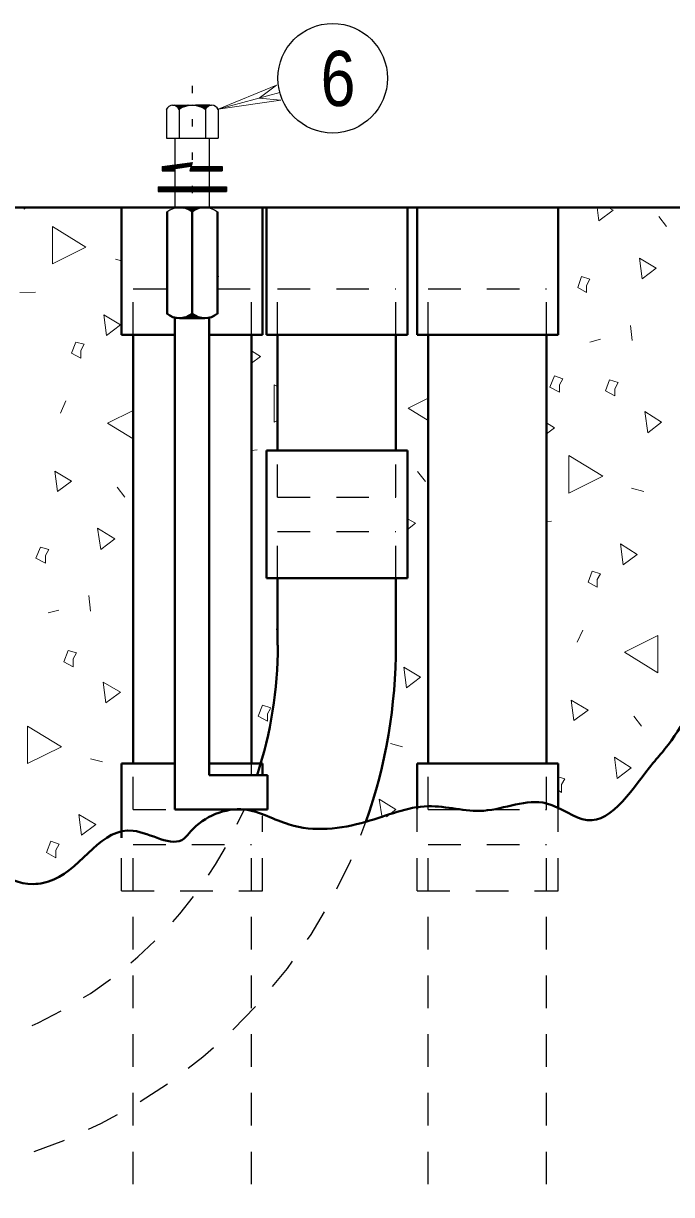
# Model space of a CAD drawing. Extents: x 312583 to 312854, y 144419 to 144597.
# Drawn here: x 312745.49 to 312754.44, y 144531.37 to 144547.52 of the extents above; entities that cross this region are included whole.
import ezdxf

# ---------------------------------------------------------------- set-up
doc = ezdxf.new("R2010")
doc.units = 0
doc.header["$LTSCALE"] = 0.3
doc.linetypes.add('DOTTED', pattern=[1.5, 0.3, -1.2])
doc.linetypes.add('SHORT_DASHED', pattern=[2.7, 1.5, -1.2])
doc.layers.add('1', color=7, linetype='Continuous', lineweight=25)
doc.layers.add('2', color=7, linetype='Continuous', lineweight=13)

msp = doc.modelspace()

# ---------------------------------------------------------------- linework, layer by layer
at = {"layer": '1', "linetype": 'DOTTED'}
msp.add_line((312747.8218, 144546.6623), (312747.8218, 144544.9833), dxfattribs=at)
at = {"layer": '1'}
for p, q in [((312747.4691, 144546.3403), (312747.4691, 144545.9416)), ((312747.5535, 144546.3939), (312748.0901, 144546.3939)), ((312747.6455, 144546.3403), (312747.6455, 144545.9416)), ((312748.0058, 144546.3403), (312748.0058, 144545.9416)), ((312748.1821, 144546.3403), (312748.1821, 144545.9416)), ((312747.4691, 144545.9416), (312748.1821, 144545.9416)), ((312747.5841, 144545.9416), (312747.5841, 144544.9833)), ((312748.0595, 144545.9416), (312748.0595, 144544.9833)), ((312747.4078, 144545.5506), (312747.4078, 144545.4893)), ((312747.8065, 144545.5506), (312748.2358, 144545.5506)), ((312748.2358, 144545.5506), (312748.2358, 144545.4893)), ((312747.7911, 144545.4893), (312748.2358, 144545.4893)), ((312747.3541, 144545.2669), (312748.2971, 144545.2669)), ((312747.3541, 144545.2669), (312747.3541, 144545.2056)), ((312747.3541, 144545.2516), (312748.2971, 144545.2516)), ((312747.3541, 144545.2363), (312748.2971, 144545.2363)), ((312747.3541, 144545.2209), (312748.2971, 144545.2209)), ((312747.3541, 144545.2056), (312748.2971, 144545.2056)), ((312748.2971, 144545.2669), (312748.2971, 144545.2056)), ((312747.5841, 144544.9833), (312748.0595, 144544.9833)), ((312747.6531, 144544.9833), (312747.9981, 144544.9833))]:
    msp.add_line(p, q, dxfattribs=at)
at = {"layer": '1', "lineweight": 40}
for p, q in [((312722.2688, 144544.9833), (312760.6021, 144544.9833)), ((312746.8481, 144543.2276), (312746.8481, 144544.9833)), ((312747.4768, 144544.9219), (312747.4768, 144543.5189)), ((312747.8218, 144544.9833), (312747.8218, 144543.4576)), ((312748.1745, 144544.9219), (312748.1745, 144543.5189)), ((312748.7955, 144543.2276), (312748.7955, 144544.9833)), ((312748.8491, 144543.2276), (312748.8491, 144544.9833)), ((312750.7965, 144543.2276), (312750.7965, 144544.9833)), ((312750.9268, 144543.2276), (312750.9268, 144544.9833)), ((312752.8741, 144543.2276), (312752.8741, 144544.9833)), ((312747.5841, 144543.4576), (312747.5841, 144536.6803)), ((312747.6531, 144543.4576), (312747.9981, 144543.4576)), ((312748.0595, 144543.4576), (312748.0595, 144537.1556)), ((312746.8481, 144543.2276), (312747.5841, 144543.2276)), ((312747.0091, 144537.3166), (312747.0091, 144543.2276)), ((312748.0595, 144543.2276), (312748.7955, 144543.2276)), ((312748.6421, 144537.3166), (312748.6421, 144543.2276)), ((312748.8491, 144543.2276), (312750.7965, 144543.2276)), ((312749.0025, 144541.6329), (312749.0025, 144543.2276)), ((312750.6355, 144541.6329), (312750.6355, 144543.2276)), ((312750.9268, 144543.2276), (312752.8741, 144543.2276)), ((312751.0801, 144537.3166), (312751.0801, 144543.2276)), ((312752.7131, 144537.3166), (312752.7131, 144543.2276)), ((312748.8491, 144539.8696), (312748.8491, 144541.6329)), ((312748.8491, 144541.6329), (312750.7965, 144541.6329)), ((312750.7965, 144539.8696), (312750.7965, 144541.6329)), ((312748.8491, 144539.8696), (312750.7965, 144539.8696)), ((312749.0025, 144538.9496), (312749.0025, 144539.8696)), ((312750.6355, 144538.9496), (312750.6355, 144539.8696)), ((312746.8481, 144537.3166), (312747.5841, 144537.3166)), ((312746.8481, 144536.2893), (312746.8481, 144537.3166)), ((312748.0595, 144537.3166), (312748.7955, 144537.3166)), ((312748.7955, 144537.1556), (312748.7955, 144537.3166)), ((312750.9268, 144537.3166), (312752.8741, 144537.3166)), ((312750.9268, 144536.6879), (312750.9268, 144537.3166)), ((312752.8741, 144536.6956), (312752.8741, 144537.3166)), ((312748.0595, 144537.1556), (312748.8645, 144537.1556)), ((312748.8645, 144537.1556), (312748.8645, 144536.6803)), ((312747.5841, 144536.6803), (312748.8645, 144536.6803))]:
    msp.add_line(p, q, dxfattribs=at)
at = {"layer": '1', "lineweight": 13}
msp.add_line((312748.1745, 144544.0403), (312748.1898, 144544.0326), dxfattribs=at)
at = {"layer": '1', "linetype": 'SHORT_DASHED'}
for p, q in [((312747.0091, 144543.2276), (312747.0091, 144543.8639)), ((312747.0091, 144543.8639), (312747.4768, 144543.8639)), ((312748.1745, 144543.8639), (312748.6421, 144543.8639)), ((312748.6421, 144543.2276), (312748.6421, 144543.8639)), ((312749.0025, 144543.8639), (312750.6355, 144543.8639)), ((312749.0025, 144543.2276), (312749.0025, 144543.8639)), ((312750.6355, 144543.2276), (312750.6355, 144543.8639)), ((312751.0801, 144543.8639), (312752.7131, 144543.8639)), ((312751.0801, 144543.2276), (312751.0801, 144543.8639)), ((312752.7131, 144543.2276), (312752.7131, 144543.8639)), ((312749.0025, 144540.9889), (312749.0025, 144541.6329)), ((312750.6355, 144540.9889), (312750.6355, 144541.6329)), ((312749.0025, 144540.9889), (312750.6355, 144540.9889)), ((312749.0025, 144540.5136), (312750.6355, 144540.5136)), ((312749.0025, 144539.8696), (312749.0025, 144540.5136)), ((312750.6355, 144539.8696), (312750.6355, 144540.5136)), ((312747.0091, 144536.6803), (312747.0091, 144537.3166)), ((312748.6421, 144537.1556), (312748.6421, 144537.3166)), ((312751.0801, 144536.6803), (312751.0801, 144537.3166)), ((312752.7131, 144536.6803), (312752.7131, 144537.3166)), ((312747.0091, 144536.6803), (312747.5841, 144536.6803)), ((312748.0595, 144536.6803), (312748.6421, 144536.6803)), ((312750.9268, 144535.5609), (312750.9268, 144536.6879)), ((312751.0801, 144536.6803), (312752.7131, 144536.6803)), ((312752.8741, 144535.5609), (312752.8741, 144536.6956)), ((312748.7955, 144535.5609), (312748.7955, 144536.5959)), ((312746.8481, 144535.5609), (312746.8481, 144536.2893)), ((312747.0091, 144535.5609), (312747.0091, 144536.1973)), ((312747.0091, 144536.1973), (312748.6421, 144536.1973)), ((312748.6421, 144535.5609), (312748.6421, 144536.1973)), ((312751.0801, 144536.1973), (312752.7131, 144536.1973)), ((312751.0801, 144535.5609), (312751.0801, 144536.1973)), ((312752.7131, 144535.5609), (312752.7131, 144536.1973)), ((312746.8481, 144535.5609), (312748.7955, 144535.5609)), ((312747.0091, 144524.2219), (312747.0091, 144535.5609)), ((312748.6421, 144524.2219), (312748.6421, 144535.5609)), ((312750.9268, 144535.5609), (312752.8741, 144535.5609)), ((312751.0801, 144524.2219), (312751.0801, 144535.5609)), ((312752.7131, 144524.2219), (312752.7131, 144535.5609))]:
    msp.add_line(p, q, dxfattribs=at)
at = {"layer": '1'}
for points in [[(312747.5765, 144546.3939), (312747.7758, 144546.3939), (312747.7451, 144546.3863), (312747.7221, 144546.3786), (312747.6838, 144546.3633), (312747.6455, 144546.3403), (312747.6301, 144546.3633), (312747.6148, 144546.3786), (312747.5841, 144546.3939), (312747.7605, 144546.3939), (312747.7145, 144546.3786), (312747.6761, 144546.3633), (312747.6455, 144546.3479), (312747.6225, 144546.3709), (312747.5995, 144546.3863), (312747.7375, 144546.3863), (312747.6915, 144546.3709), (312747.6455, 144546.3479), (312747.6071, 144546.3863), (312747.7221, 144546.3863), (312747.6455, 144546.3556), (312747.6148, 144546.3863), (312747.7145, 144546.3863), (312747.6455, 144546.3556), (312747.6225, 144546.3786), (312747.6991, 144546.3786), (312747.6455, 144546.3633), (312747.6301, 144546.3786), (312747.6761, 144546.3786), (312747.6455, 144546.3709), (312747.6378, 144546.3786), (312747.6608, 144546.3786), (312747.6455, 144546.3709)], [(312748.0671, 144546.3939), (312747.8678, 144546.3939), (312747.9061, 144546.3863), (312747.9291, 144546.3786), (312747.9675, 144546.3633), (312748.0058, 144546.3403), (312748.0135, 144546.3633), (312748.0288, 144546.3786), (312748.0595, 144546.3939), (312747.8831, 144546.3939), (312747.9368, 144546.3786), (312747.9751, 144546.3633), (312747.9981, 144546.3479), (312748.0288, 144546.3709), (312748.0518, 144546.3863), (312747.9061, 144546.3863), (312747.9598, 144546.3709), (312747.9981, 144546.3479), (312748.0365, 144546.3863), (312747.9215, 144546.3863), (312748.0058, 144546.3556), (312748.0365, 144546.3863), (312747.9368, 144546.3863), (312748.0058, 144546.3556), (312748.0211, 144546.3786), (312747.9521, 144546.3786), (312748.0058, 144546.3633), (312748.0135, 144546.3786), (312747.9675, 144546.3786), (312747.9981, 144546.3709), (312748.0058, 144546.3786), (312747.9905, 144546.3786), (312747.9981, 144546.3709)], [(312747.4078, 144545.5506), (312747.8218, 144545.6043), (312747.7911, 144545.4893)], [(312747.8065, 144545.5506), (312747.4078, 144545.4893), (312747.5841, 144545.4893)], [(312747.5841, 144545.4893), (312747.4155, 144545.4969), (312747.4155, 144545.5429), (312747.8141, 144545.5966), (312747.7988, 144545.5506), (312747.5841, 144545.5199), (312747.5765, 144545.4969), (312747.4231, 144545.5046), (312747.4231, 144545.5353), (312747.8065, 144545.5889), (312747.7911, 144545.5583), (312747.5765, 144545.5199), (312747.5688, 144545.5046), (312747.4231, 144545.5123), (312747.4231, 144545.5276), (312747.7911, 144545.5813), (312747.7911, 144545.5659), (312747.5765, 144545.5276), (312747.5611, 144545.5199), (312747.5151, 144545.5123), (312747.4385, 144545.5199), (312747.7758, 144545.5736), (312747.4921, 144545.5199)], [(312747.7988, 144545.4969), (312748.2281, 144545.4969), (312748.2281, 144545.5429), (312747.8141, 144545.5353), (312747.7988, 144545.5046), (312748.2205, 144545.5046), (312748.2205, 144545.5353), (312747.8218, 144545.5276), (312747.8065, 144545.5123), (312748.2128, 144545.5123), (312748.2128, 144545.5276), (312748.2051, 144545.5276), (312747.8218, 144545.5276), (312747.8141, 144545.5199), (312748.2051, 144545.5199)], [(312747.6991, 144544.9833), (312747.9521, 144544.9833), (312747.9291, 144544.9756), (312747.8985, 144544.9679), (312747.8678, 144544.9526), (312747.8525, 144544.9449), (312747.8295, 144544.9296), (312747.8218, 144544.9219), (312747.7758, 144544.9603), (312747.7298, 144544.9756), (312747.7068, 144544.9756), (312747.9368, 144544.9833), (312747.9215, 144544.9756), (312747.8985, 144544.9756), (312747.8678, 144544.9603), (312747.8371, 144544.9449), (312747.8295, 144544.9373), (312747.8218, 144544.9296), (312747.7835, 144544.9603), (312747.7298, 144544.9756), (312747.9061, 144544.9756), (312747.8601, 144544.9603), (312747.8218, 144544.9373), (312747.7528, 144544.9756), (312747.8831, 144544.9756), (312747.8218, 144544.9373), (312747.7681, 144544.9679), (312747.8755, 144544.9756), (312747.8295, 144544.9449), (312747.7911, 144544.9679), (312747.8525, 144544.9679), (312747.8218, 144544.9603), (312747.7835, 144544.9603), (312747.8065, 144544.9526), (312747.8141, 144544.9679), (312747.8218, 144544.9449), (312747.8371, 144544.9603), (312747.8448, 144544.9603), (312747.8601, 144544.9679)]]:
    msp.add_lwpolyline(points, dxfattribs=at)
at = {"layer": '1', "lineweight": 40}
msp.add_lwpolyline([(312747.6991, 144543.4576), (312747.9521, 144543.4576), (312747.9291, 144543.4653), (312747.8985, 144543.4729), (312747.8678, 144543.4883), (312747.8525, 144543.4959), (312747.8295, 144543.5113), (312747.8218, 144543.5189), (312747.7758, 144543.4806), (312747.7298, 144543.4653), (312747.7068, 144543.4653), (312747.9368, 144543.4576), (312747.9215, 144543.4653), (312747.8985, 144543.4653), (312747.8678, 144543.4806), (312747.8371, 144543.4959), (312747.8295, 144543.5036), (312747.8218, 144543.5113), (312747.7835, 144543.4806), (312747.7298, 144543.4653), (312747.9061, 144543.4653), (312747.8601, 144543.4806), (312747.8218, 144543.5036), (312747.7528, 144543.4653), (312747.8831, 144543.4653), (312747.8218, 144543.5036), (312747.7681, 144543.4729), (312747.8755, 144543.4653), (312747.8295, 144543.4959), (312747.7911, 144543.4729), (312747.8525, 144543.4729), (312747.8218, 144543.4806), (312747.7835, 144543.4729), (312747.8065, 144543.4883), (312747.8141, 144543.4729), (312747.8218, 144543.4959), (312747.8371, 144543.4806), (312747.8448, 144543.4806), (312747.8601, 144543.4729)], dxfattribs=at)
at = {"layer": '1'}
for centre, radius, start, end in [((312747.5551, 144546.2937), 0.0993, 25.60064, 154.39936), ((312747.8237, 144546.0804), 0.3126, 55.04559, 124.95441), ((312748.0924, 144546.2937), 0.0993, 25.60064, 154.39936), ((312747.6489, 144544.7112), 0.272, 50.00693, 129.99306), ((312747.9985, 144544.7112), 0.272, 50.00694, 129.99307)]:
    msp.add_arc(centre, radius, start, end, dxfattribs=at)
at = {"layer": '1', "lineweight": 40}
for centre, radius, start, end in [((312747.6489, 144543.7285), 0.272, 230.00694, 309.99307), ((312747.9985, 144543.7285), 0.272, 230.00693, 309.99306), ((312743.2557, 144538.9458), 5.75, 341.8604, 0), ((312743.2557, 144538.9458), 7.3792, 340.73599, 0)]:
    msp.add_arc(centre, radius, start, end, dxfattribs=at)
at = {"layer": '1', "linetype": 'SHORT_DASHED'}
for radius, end in [(5.75, 336.76867), (7.3792, 340.7336)]:
    msp.add_arc((312743.2557, 144538.9458), radius, 270, end, dxfattribs=at)
at = {"layer": '1', "lineweight": 40}
msp.add_spline([(312755.0745, 144544.9833), (312755.5728, 144544.1169), (312756.1785, 144543.2276), (312755.8258, 144542.1543), (312755.2585, 144541.7173), (312755.0055, 144540.7973), (312754.8828, 144538.5893), (312754.3461, 144537.5159), (312754.1851, 144537.3243), (312753.2728, 144536.5346), (312752.7131, 144536.7646), (312751.8468, 144536.6649), (312751.0801, 144536.7263), (312750.2215, 144536.5116), (312749.1635, 144536.4733), (312748.5425, 144536.6803), (312747.8065, 144536.3813), (312747.7145, 144536.2816), (312747.0091, 144536.3889), (312745.9128, 144535.7143), (312745.6291, 144535.6529), (312744.5635, 144536.2126), (312742.9688, 144536.2893), (312742.6315, 144535.8293)], degree=3, dxfattribs=at)
at = {"layer": '2'}
for p, q in [((312748.1821, 144546.3403), (312748.9871, 144546.6699)), ((312748.9871, 144546.6699), (312748.7495, 144546.4936)), ((312749.0331, 144546.5703), (312748.1821, 144546.3403)), ((312749.0485, 144546.4629), (312748.7495, 144546.4936)), ((312748.1821, 144546.3403), (312749.0485, 144546.4629)), ((312745.4988, 144544.9833), (312745.5065, 144544.9603)), ((312745.5065, 144544.9603), (312745.5295, 144544.9833)), ((312753.4108, 144544.9833), (312753.4338, 144544.7993)), ((312754.2618, 144544.8606), (312754.3691, 144544.7226)), ((312746.7638, 144544.2703), (312746.8481, 144544.2473)), ((312745.4451, 144543.8103), (312745.6598, 144543.8179)), ((312753.8708, 144543.3579), (312753.8938, 144543.1509)), ((312753.3111, 144543.1279), (312753.4568, 144543.1663)), ((312749.0025, 144542.5146), (312748.9565, 144542.5376)), ((312746.0815, 144542.3153), (312746.0048, 144542.1466)), ((312748.6421, 144541.6329), (312748.7188, 144541.6406)), ((312750.9345, 144541.3416), (312751.0418, 144541.2036)), ((312746.7868, 144541.1269), (312746.8941, 144540.9889)), ((312753.8861, 144541.1116), (312754.0548, 144541.0656)), ((312752.7131, 144540.6516), (312752.7821, 144540.6593)), ((312746.3958, 144539.6319), (312746.4188, 144539.4173)), ((312745.8361, 144539.3943), (312745.9818, 144539.4326)), ((312753.2115, 144539.1566), (312753.1348, 144538.9879)), ((312748.8645, 144537.9989), (312748.9028, 144538.0756)), ((312753.9168, 144537.9683), (312754.0241, 144537.8303)), ((312750.5588, 144537.5926), (312750.7275, 144537.5466)), ((312746.4188, 144537.3779), (312746.5875, 144537.3396))]:
    msp.add_line(p, q, dxfattribs=at)
for points in [[(312753.4338, 144544.7993), (312753.6331, 144544.9449), (312753.5641, 144544.9833)], [(312748.6421, 144542.8366), (312748.7648, 144542.9286), (312748.6421, 144543.0053)], [(312748.9565, 144542.5376), (312748.9565, 144542.0239), (312749.0025, 144542.0469)], [(312751.0801, 144542.3536), (312750.8041, 144542.2156), (312751.0801, 144542.0469)], [(312747.0091, 144542.1849), (312746.6565, 144542.0086), (312747.0091, 144541.7939)], [(312752.7131, 144541.8629), (312752.8205, 144541.9473), (312752.7131, 144542.0163)], [(312750.7965, 144540.5443), (312750.9038, 144540.6286), (312750.7965, 144540.6899)], [(312749.0025, 144539.1643), (312748.9871, 144539.1719), (312749.0025, 144539.0646)], [(312748.9105, 144538.0833), (312748.7955, 144538.1216), (312748.7341, 144537.9683), (312748.8645, 144537.8993), (312748.8645, 144537.9989)], [(312752.9201, 144537.0253), (312752.9661, 144537.1019), (312752.8741, 144537.1326)], [(312752.8741, 144536.9486), (312752.9201, 144536.9179), (312752.9201, 144537.0253)], [(312750.5051, 144536.5806), (312750.6355, 144536.6803), (312750.4055, 144536.8259), (312750.4438, 144536.5653)]]:
    msp.add_lwpolyline(points, dxfattribs=at)
for points in [[(312745.8975, 144544.7226), (312745.8975, 144544.2089), (312746.3575, 144544.4389)], [(312754.0318, 144544.0019), (312754.2235, 144544.1476), (312753.9935, 144544.2856)], [(312753.2651, 144543.9099), (312753.3111, 144543.9943), (312753.1961, 144544.0326), (312753.1425, 144543.8793), (312753.2651, 144543.8103)], [(312746.6411, 144543.2199), (312746.8328, 144543.3656), (312746.6028, 144543.5036)], [(312746.2885, 144543.0129), (312746.3345, 144543.0973), (312746.2195, 144543.1279), (312746.1581, 144542.9746), (312746.2885, 144542.9056)], [(312752.8895, 144542.5376), (312752.9355, 144542.6219), (312752.8205, 144542.6603), (312752.7591, 144542.5069), (312752.8895, 144542.4379)], [(312753.6561, 144542.4839), (312753.7021, 144542.5683), (312753.5795, 144542.6066), (312753.5258, 144542.4533), (312753.6561, 144542.3843)], [(312754.1085, 144541.8783), (312754.3001, 144542.0239), (312754.0701, 144542.1696)], [(312753.0198, 144541.5639), (312753.0198, 144541.0426), (312753.4875, 144541.2803)], [(312745.9665, 144541.0656), (312746.1581, 144541.2113), (312745.9281, 144541.3493)], [(312746.5645, 144540.2683), (312746.7561, 144540.4139), (312746.5185, 144540.5596)], [(312753.7711, 144540.0536), (312753.9628, 144540.1993), (312753.7328, 144540.3449)], [(312745.7978, 144540.1839), (312745.8438, 144540.2683), (312745.7288, 144540.2989), (312745.6675, 144540.1456), (312745.7978, 144540.0766)], [(312753.4108, 144539.8543), (312753.4568, 144539.9309), (312753.3418, 144539.9693), (312753.2881, 144539.8159), (312753.4108, 144539.7469)], [(312754.2465, 144538.5663), (312754.2465, 144539.0799), (312753.7865, 144538.8499)], [(312746.1811, 144538.7579), (312746.2271, 144538.8423), (312746.1121, 144538.8729), (312746.0508, 144538.7196), (312746.1811, 144538.6506)], [(312750.7811, 144538.3593), (312750.9728, 144538.5049), (312750.7428, 144538.6429)], [(312746.6335, 144538.1523), (312746.8328, 144538.2979), (312746.5951, 144538.4359)], [(312753.0888, 144537.9069), (312753.2881, 144538.0526), (312753.0505, 144538.1906)], [(312745.5525, 144537.8303), (312745.5525, 144537.3166), (312746.0201, 144537.5466)], [(312753.6868, 144537.1096), (312753.8785, 144537.2553), (312753.6485, 144537.4009)], [(312746.2961, 144536.3276), (312746.4955, 144536.4733), (312746.2578, 144536.6113)], [(312745.9435, 144536.1206), (312745.9895, 144536.2049), (312745.8745, 144536.2433), (312745.8131, 144536.0899), (312745.9435, 144536.0133)]]:
    msp.add_lwpolyline(points, close=True, dxfattribs=at)
at = {"layer": '2', "lineweight": 25}
msp.add_circle((312749.7621, 144546.767), 0.7557, dxfattribs=at)

# ---------------------------------------------------------------- texts
at = {"layer": '2', "width": 0.85}
msp.add_text('6', height=0.76, dxfattribs=at).set_placement((312749.5958, 144546.3835))

doc.saveas('drawing.dxf')
